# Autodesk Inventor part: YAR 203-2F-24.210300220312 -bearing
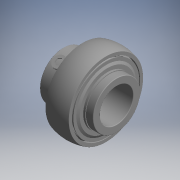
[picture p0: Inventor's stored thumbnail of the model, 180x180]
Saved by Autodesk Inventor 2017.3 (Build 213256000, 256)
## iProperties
Part Number: YAR 203-2F-24.210300220312 -bearing
Material: Generic
Catalog Web Link: www.cadenas.de
Description: ayf_001hc_hh_hy_bearing-Y-bearings
Vendor: SKF
Document SubType Name: Modeling
Designer: partserver
Manufacturer: SKF
Mass: 10.89 g
Surface Area: 132.841 cm^2
Volume: 10.89 cm^3
Density: 1 g/cm^3
Appearance: PSOLRGB-175-175-175
Category: PARTsolutions
Company: SKF
Title: YAR 203-2F-24.210300220312 -bearing
Author: Cadenas PARTsolutions
Comments: Y-bearings
PSOL_IDENT_0: {$CADENAS_DATA\23d-libs\skf\bearings_units_and_housings\bearing_units\ball_bearing_units\y-units\y-b
PSOL_IDENT_1: earing_square_flanged_units_parts\ayf_001hc_hh_hy_bearing.prj},229 {VTYP=3D},{NB=YAR 203-2F-24.21030
PSOL_IDENT_2: 0220312 -bearing},{LINA=YAR 203-2F-24.210300220312 -bearing},{NN=ayf_001hc_hh_hy_bearing},{DATE=20.0
PSOL_IDENT_3: 8.2020 13:45:20},{GEOMDATE=29.07.2020 17:09:33},{VERSION=},{LINEID=1230},{WBVAR=},{WBNUMERIC=}  {NB=
PSOL_IDENT_4: YAR 203-2F-24.210300220312 -bearing},{LINA=YAR 203-2F-24.210300220312 -bearing},{KT=DUMMY},{PRODUCTI
PSOL_IDENT_5: D=103002203},{DESIGNATION=YAR 203-2F},{DD=17.0000},{D=40},{B=27.400},{C=12.000},{PITCH=28.500},{DW=6
PSOL_IDENT_6: .747},{FO=IEC_BBY_006},{DESIGN=ybrg1},{B1=MIN},{LM=Grub screw},{DES=Inner ring extended on both side
PSOL_IDENT_7: s},{PS=For agricultural applications},{MAT=},{SS=Standard seals with additional flingers},{UNIT=Metr
PSOL_IDENT_8: ic},{G=MIN},{DD1=24.20},{DD2=MIN},{DD3=MIN},{B3=0.000},{B4=MIN},{BB4=4.0},{R12=0.3},{R12X=0},{SS1=15
PSOL_IDENT_9: .900},{NOTE=},{DG=MIN},{E=3.600},{F=1.300},{RG=MIN},{LOAD1=9.560},{LOAD2=4.750},{LOAD3=0.200},{SPEED
PSOL_IDENT_10: 2=9500},{FF0=13},{BF=1},{A15=500000},{A8=400000},{A4=300000},{BETA=1.89},{SBT1=0.094},{SBT2=},{RF1=0
PSOL_IDENT_11: .00000039},{RF2=1.7},{SF1=0.00323},{SF2=36.5},{KZ=3.1},{II=1},{Z=8},{SG=VT307},{MASS=0.10},{G2=M6x0.
PSOL_IDENT_12: 75},{HEX=3.000},{RTT=4},{MKIT=},{AS=},{TANGLE=},{SLEEVE=},{SRING=RIS 203},{FPC=RBC17_YBRG_001},{POPI=
PSOL_IDENT_13: 1},{NOUN=N020},{NOUNDES=Ball bearing},{MOD=M200},{MODDES=Radial deep groove},{YZ=12.1},{PIM=YAR 203-
PSOL_IDENT_14: 2F},{LNDD11=MIN},{LUB3=0},{BZ=0.3502},{SDALG=h},{YRZ=17.6235},{SHAPE=4},{LNB1HM11=0},{LWM=0},{TYPEID=
PSOL_IDENT_15: 103002},{LUBGR2=0},{LOCKNUT=},{LOCKDEVICE=},{LNB=MIN},{BB=MIN},{LNB1=MIN},{S1ALG=15.9},{HH=MIN},{LDB=
PSOL_IDENT_16: MIN},{LDDD1=MIN},{LDDD2=MIN},{LDM=MIN},{LDFF=MIN},{TP=4},{LNBHM11=0},{BBHM11=0},{LNDD1HM11=0},{HELP=
PSOL_IDENT_17: 5},{HHHM11=0},{LUBGR1=0},{LWV=0},{S2=21.1},{LUB2=1},{BZ1=0.000},{HEX2=}
NB: YAR 203-2F-24.210300220312 -bearing
NN: ayf_001hc_hh_hy_bearing
NT: Y-bearings
NBSYN: $DESIGNATION.-$DD1.$PRODUCTID.$C.$B1.-bearing
LINA: YAR 203-2F-24.210300220312 -bearing
CATALOG: SKF
DESIGNATION: YAR 203-2F
DD: 17
D: 40
B: 27.4
C: 12
B1: 0
DD1: 24.2
LOAD1: 9.56
LOAD2: 4.75
LOAD3: 0.2
SPEED2: 9500
SUPPLIER: SKF
ARTICLENO: YAR 203-2F-24.210300220312 -bearing
BOMINFO: YAR 203-2F-24.210300220312 -bearing
CREATOR: CADENAS GmbH
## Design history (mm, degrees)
sketch "Sketch_1"
  geometry: L1 (50, 0)-(-50, 0); L2 (-11.2, 8.5)-(15.6, 8.5); L3 (15.9, 8.8)-(15.9, 11.8); L4 (15.6, 12.1)-(2.6, 12.1); L5 (-2.6, 12.1)-(-11.2, 12.1); L6 (-11.5, 11.8)-(-11.5, 8.8); A1 r 0.3 centre (-11.2, 8.8) between (-11.5, 8.8) and (-11.2, 8.5); A2 r 0.3 centre (15.6, 8.8) between (15.6, 8.5) and (15.9, 8.8); A3 r 0.3 centre (15.6, 11.8) between (15.9, 11.8) and (15.6, 12.1); A4 r 3.374 centre (0, 14.25) between (-2.6, 12.1) and (2.6, 12.1); A5 r 0.3 centre (-11.2, 11.8) between (-11.2, 12.1) and (-11.5, 11.8)
  constraints: 12 end point, 10 point on circle, 5 centre point
revolve "Revolution1" sketch "Sketch_1" stored, may be unused: angle "d0" = 360 deg
sketch "Sketch_2"
  geometry: L1 (10.4, -0.866)-(11.9, -1.732); L2 (11.9, -1.732)-(13.4, -0.866); L3 (13.4, -0.866)-(13.4, 0.866); L4 (13.4, 0.866)-(11.9, 1.732); L5 (11.9, 1.732)-(10.4, 0.866); L6 (10.4, 0.866)-(10.4, -0.866); C1 r 3 at (11.9, 0); 1 further point
  constraints: 12 end point, 1 centre point
extrude "Extrusion1" join sketch "Sketch_2" distance "d1" = 3.96; taper "d2" = 0 deg
sketch "Sketch_3"
  geometry: L1 (10.4, -0.866)-(11.9, -1.732); L2 (11.9, -1.732)-(13.4, -0.866); L3 (13.4, -0.866)-(13.4, 0.866); L4 (13.4, 0.866)-(11.9, 1.732); L5 (11.9, 1.732)-(10.4, 0.866); L6 (10.4, 0.866)-(10.4, -0.866); C1 r 3 at (11.9, 0); 1 further point
  constraints: 12 end point, 1 centre point
extrude "Extrusion2" join sketch "Sketch_3" distance "d3" = 3.96; taper "d4" = 0 deg
sketch "Sketch_4"
  geometry: L1 (6, 0)-(-6, 0); L2 (-7.835, 12.45)-(-7.835, 12.1); L3 (-7.835, 12.1)-(-6.435, 12.1); L4 (-6.435, 12.1)-(-6.435, 14.25); L5 (-6.435, 14.25)-(-5.825, 15.374); L6 (-5.825, 15.374)-(-5.825, 16.948); L7 (-5.825, 16.948)-(-6.175, 16.948); L8 (-6.175, 16.948)-(-6.175, 15.374); L9 (-6.175, 15.374)-(-6.785, 14.25); L10 (-6.785, 14.25)-(-6.785, 12.45); L11 (-6.785, 12.45)-(-7.835, 12.45)
  constraints: 22 end point
revolve "Revolution2" sketch "Sketch_4" stored, may be unused: angle "d5" = 360 deg
sketch "Sketch_5"
  geometry: L1 (6, 0)-(-6, 0); L2 (5.825, 16.948)-(5.825, 15.374); L3 (5.825, 15.374)-(6.435, 14.25); L4 (6.435, 14.25)-(6.435, 12.1); L5 (6.435, 12.1)-(7.835, 12.1); L6 (7.835, 12.1)-(7.835, 12.45); L7 (7.835, 12.45)-(6.785, 12.45); L8 (6.785, 12.45)-(6.785, 14.25); L9 (6.785, 14.25)-(6.175, 15.374); L10 (6.175, 15.374)-(6.175, 16.948); L11 (6.175, 16.948)-(5.825, 16.948)
  constraints: 22 end point
revolve "Revolution3" sketch "Sketch_5" stored, may be unused: angle "d6" = 360 deg
sketch "Sketch_6"
  geometry: L1 (50, 0)-(-50, 0); L2 (-6, 14.822)-(-6, 12.431); L3 (-6, 12.431)-(-5.65, 12.431); L4 (-5.65, 12.431)-(-5.65, 14.638); L5 (-5.65, 14.638)-(-4.194, 15.643); L6 (-4.194, 15.643)-(-4.154, 15.585); L7 (-4.154, 15.585)-(-5.58, 14.601); L8 (-5.58, 14.601)-(-5.58, 12.597); L9 (-5.58, 12.597)-(-4.261, 12.597); L10 (-4.261, 12.597)-(-4.366, 12.1); L11 (-4.366, 12.1)-(-4.016, 12.1); L12 (-4.016, 12.1)-(-3.899, 12.652); L13 (-3.899, 12.652)-(-3.899, 13.205); L14 (-3.899, 13.205)-(-4.366, 13.757); L15 (-4.366, 13.757)-(-4.366, 14.862); L16 (-4.366, 14.862)-(-3.899, 15.414); L17 (-3.899, 15.414)-(-3.899, 17.507); L18 (-4.016, 17.623)-(-4.132, 17.623); L19 (-4.249, 17.507)-(-4.867, 16.77); L20 (-4.867, 16.77)-(-4.599, 16.545); L21 (-4.599, 16.545)-(-4.249, 16.962); L22 (-4.249, 16.962)-(-4.249, 16.031); L23 (-4.249, 16.031)-(-6, 14.822); A1 r 0.117 centre (-4.016, 17.507) between (-3.899, 17.507) and (-4.016, 17.623); A2 r 0.117 centre (-4.132, 17.507) between (-4.132, 17.623) and (-4.249, 17.507)
  constraints: 46 end point, 4 point on circle, 2 centre point
revolve "Revolution4" sketch "Sketch_6" stored, may be unused: angle "d7" = 360 deg
sketch "Sketch_11"
  geometry: L1 (50, 0)-(-50, 0); L2 (3.899, 17.507)-(3.899, 15.414); L3 (3.899, 15.414)-(4.366, 14.862); L4 (4.366, 14.862)-(4.366, 13.757); L5 (4.366, 13.757)-(3.899, 13.205); L6 (3.899, 13.205)-(3.899, 12.652); L7 (3.899, 12.652)-(4.016, 12.1); L8 (4.016, 12.1)-(4.366, 12.1); L9 (4.366, 12.1)-(4.261, 12.597); L10 (4.261, 12.597)-(5.58, 12.597); L11 (5.58, 12.597)-(5.58, 14.601); L12 (5.58, 14.601)-(4.154, 15.585); L13 (4.154, 15.585)-(4.194, 15.643); L14 (4.194, 15.643)-(5.65, 14.638); L15 (5.65, 14.638)-(5.65, 12.431); L16 (5.65, 12.431)-(6, 12.431); L17 (6, 12.431)-(6, 14.822); L18 (6, 14.822)-(4.249, 16.031); L19 (4.249, 16.031)-(4.249, 16.962); L20 (4.249, 16.962)-(4.599, 16.545); L21 (4.599, 16.545)-(4.867, 16.77); L22 (4.867, 16.77)-(4.249, 17.507); L23 (4.132, 17.623)-(4.016, 17.623); A1 r 0.117 centre (4.132, 17.507) between (4.249, 17.507) and (4.132, 17.623); A2 r 0.117 centre (4.016, 17.507) between (4.016, 17.623) and (3.899, 17.507)
  constraints: 46 end point, 4 point on circle, 2 centre point
revolve "Revolution5" sketch "Sketch_11" stored, may be unused: angle "d8" = 360 deg
sketch "Sketch_16"
  geometry: L1 (6, 0)-(-6, 0); L2 (-6, 17.473)-(-4.322, 17.473); L3 (-4.322, 17.473)-(-4.189, 17.575); L4 (-3.887, 17.459)-(-3.82, 17.111); L5 (-3.624, 16.949)-(-2.107, 16.949); L6 (2.107, 16.949)-(3.624, 16.949); L7 (3.82, 17.111)-(3.887, 17.459); L8 (4.189, 17.575)-(4.322, 17.473); L9 (4.322, 17.473)-(6, 17.473); L10 (6, 17.473)-(6, 19.005); L11 (-6, 19.005)-(-6, 17.473); A1 r 0.19 centre (-4.074, 17.423) between (-3.887, 17.459) and (-4.189, 17.575); A2 r 0.2 centre (-3.624, 17.149) between (-3.82, 17.111) and (-3.624, 16.949); A3 r 0.254 centre (-2.107, 17.203) between (-2.107, 16.949) and (-1.96, 16.996); A4 r 3.374 centre (0, 14.25) between (1.96, 16.996) and (-1.96, 16.996); A5 r 0.254 centre (2.107, 17.203) between (1.96, 16.996) and (2.107, 16.949); A6 r 0.2 centre (3.624, 17.149) between (3.624, 16.949) and (3.82, 17.111); A7 r 0.19 centre (4.074, 17.423) between (4.189, 17.575) and (3.887, 17.459); A8 r 0.1 centre (5.9, 19.005) between (6, 19.005) and (5.93, 19.101); A9 r 20 centre (0, 0) between (5.93, 19.101) and (-5.93, 19.101); A10 r 0.1 centre (-5.9, 19.005) between (-5.93, 19.101) and (-6, 19.005)
  constraints: 22 end point, 20 point on circle, 10 centre point
revolve "Revolution6" sketch "Sketch_16" stored, may be unused: angle "d9" = 360 deg
sketch "Sketch_21"
  geometry: L1 (-2.925, 14.25)-(-2.925, 28.5); L2 (-2.925, 28.5)-(-2.275, 28.5); L3 (-2.275, 28.5)-(-2.275, 14.25); L4 (-2.275, 14.25)-(-2.925, 14.25); L5 (-2.925, 14.25)-(-2.925, 28.5)
  constraints: 10 end point
revolve "Revolution7" sketch "Sketch_21" stored, may be unused: angle "d10" = 360 deg
node "ball_1_XY"
node "ball_1_YZ"
node "ball_1_ZX"
node "ball_1_X"
node "ball_1_Y"
node "ball_1_Z"
node "ball_1_Center"
node "ball_2_XY"
node "ball_2_YZ"
node "ball_2_ZX"
node "ball_2_X"
node "ball_2_Y"
node "ball_2_Z"
node "ball_2_Center"
node "ball_3_XY"
node "ball_3_YZ"
node "ball_3_ZX"
node "ball_3_X"
node "ball_3_Y"
node "ball_3_Z"
node "ball_3_Center"
node "ball_4_XY"
node "ball_4_YZ"
node "ball_4_ZX"
node "ball_4_X"
node "ball_4_Y"
node "ball_4_Z"
node "ball_4_Center"
node "ball_5_XY"
node "ball_5_YZ"
node "ball_5_ZX"
node "ball_5_X"
node "ball_5_Y"
node "ball_5_Z"
node "ball_5_Center"
node "ball_6_XY"
node "ball_6_YZ"
node "ball_6_ZX"
node "ball_6_X"
node "ball_6_Y"
node "ball_6_Z"
node "ball_6_Center"
node "ball_7_XY"
node "ball_7_YZ"
node "ball_7_ZX"
node "ball_7_X"
node "ball_7_Y"
node "ball_7_Z"
node "ball_7_Center"
node "ball_8_XY"
node "ball_8_YZ"
node "ball_8_ZX"
node "ball_8_X"
node "ball_8_Y"
node "ball_8_Z"
node "ball_8_Center"
node "brg_XY"
node "brg_YZ"
node "brg_ZX"
node "brg_X"
node "brg_Y"
node "brg_Z"
node "brg_Center"
node "brg3_XY"
node "brg3_YZ"
node "brg3_ZX"
node "brg3_X"
node "brg3_Y"
node "brg3_Z"
node "brg3_Center"
body "Solid1"
other parameters: "d11" = 0
